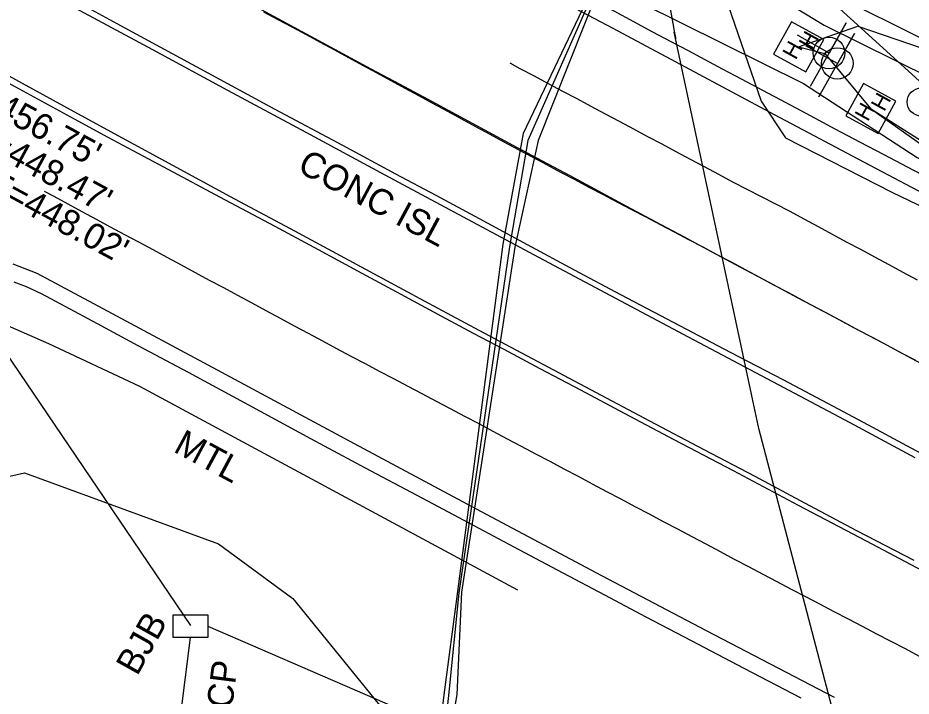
# Model space of a CAD drawing. Extents: x 2074109 to 2077820, y 741079 to 746031.
# Drawn here: x 2075958.1 to 2076097, y 743030.4 to 743136 of the extents above; entities that cross this region are included whole.
import ezdxf

# ---------------------------------------------------------------- set-up
doc = ezdxf.new("R2010")
doc.units = 0
for name, color, linetype in [('Exist Guardrail', 7, 'Continuous'), ('Exist Guardrail Text', 7, 'Continuous'), ('Exist Horizontal Alignment', 7, 'Continuous'), ('Exist Other Culture Anchor (Guy Wire) CELL', 7, 'Continuous'), ('Exist Roads Curbs', 7, 'Continuous'), ('Exist Roads Curbs Text', 7, 'Continuous'), ('Exist Roads EOP', 7, 'Continuous'), ('Exist Roads EOT', 7, 'Continuous'), ('Exist Structure Minor Drop Inlet Top Elevation', 7, 'Continuous'), ('Exist Structure Minor Junction Box', 7, 'Continuous'), ('Exist Structure Minor Junction Box Text', 7, 'Continuous'), ('Exist Structure Minor Pipes RCP 18 Inch Invert', 7, 'Continuous'), ('Exist Structure Minor Pipes RCP 36 Inch', 7, 'Continuous'), ('Exist Structure Minor Pipes RCP 36 Inch Text', 7, 'Continuous'), ('Exist Structure Minor Pipes RCP 42 Inch', 7, 'Continuous'), ('Exist Utilities Gas UG Line SUE LOS B', 7, 'Continuous'), ('Exist Utilities Power Joint Use Telephone CELL', 7, 'Continuous'), ('Exist Utilities Power UG Cable SUE LOS B', 7, 'Continuous'), ('Exist Utilities Telephone UG Conduit SUE LOS B', 7, 'Continuous'), ('Exist Utilities Telephone UG FO SUE LOS B', 7, 'Continuous'), ('Exist Utilities TV Hand Hole CELL', 7, 'Continuous'), ('Exist Utilities TV UG FO Cable SUE LOS B', 7, 'Continuous'), ('Exist Utilities Water UG Line SUE LOS B', 7, 'Continuous'), ('Exist Vegetation Woods Line', 7, 'Continuous')]:
    doc.layers.add(name, color=color, linetype=linetype)

msp = doc.modelspace()

# ---------------------------------------------------------------- linework, layer by layer
at = {"layer": 'Exist Guardrail'}
msp.add_lwpolyline([(2076035.85, 743046.89), (2075977.06, 743078.6), (2075962.92, 743085.25), (2075954.84, 743088.74), (2075948.86, 743090.68), (2075941.12, 743092.48), (2075934.11, 743092.47), (2075927.39, 743091.26), (2075921.51, 743089.22), (2075916.19, 743086.74), (2075911.7, 743083.21), (2075906.18, 743077.24), (2075900.02, 743069.91)], dxfattribs=at)
at = {"layer": 'Exist Horizontal Alignment'}
msp.add_arc((2085431.66, 760592.33), 19842.16, 241.357198, 242.284762, dxfattribs=at)
at = {"layer": 'Exist Other Culture Anchor (Guy Wire) CELL'}
msp.add_circle((2076098.61, 743122.88), 2.18, dxfattribs=at)
at = {"layer": 'Exist Roads Curbs'}
for points in [[(2075956.65, 743143.13), (2075967.73, 743137.15), (2075979.01, 743131.05), (2075990.69, 743124.74), (2076002.87, 743118.19), (2076015.18, 743111.57), (2076027.37, 743105.02), (2076039.05, 743098.75), (2076050.28, 743092.74), (2076062.34, 743086.33), (2076075.49, 743079.38), (2076087.5, 743072.99), (2076097.63, 743067.52)], [(2076041.74, 743142.01), (2076046.99, 743139.13), (2076050.79, 743137.06), (2076053.85, 743135.42), (2076056.83, 743133.83), (2076059.68, 743132.31), (2076062.34, 743130.9), (2076064.95, 743129.51), (2076067.65, 743128.07), (2076070.59, 743126.5), (2076073.92, 743124.72), (2076077.53, 743122.8), (2076081.31, 743120.78), (2076085.18, 743118.73), (2076089.03, 743116.7), (2076092.8, 743114.71), (2076096.45, 743112.79), (2076099.9, 743110.97)], [(2076097.52, 743051.5), (2076088.62, 743056.12), (2076080.48, 743060.44), (2076072.77, 743064.56), (2076064.86, 743068.74), (2076056.4, 743073.2), (2076047.22, 743078.06), (2076038.15, 743082.9), (2076029.87, 743087.32), (2076021.35, 743091.89), (2076011.53, 743097.17), (2076001.15, 743102.76), (2075991.19, 743108.12), (2075982.18, 743112.99), (2075974.38, 743117.24), (2075966.86, 743121.36), (2075958.81, 743125.75), (2075951.51, 743129.74)], [(2076079.91, 743030.08), (2076071.08, 743034.69), (2076062.88, 743038.99), (2076055.83, 743042.7), (2076049.37, 743046.13), (2076042.92, 743049.54), (2076036.05, 743053.19), (2076028.3, 743057.3), (2076020.18, 743061.62), (2076012.17, 743065.89), (2076003.67, 743070.46), (2075994.02, 743075.67), (2075984.61, 743080.75), (2075976.79, 743084.95), (2075970.45, 743088.36), (2075965.44, 743091.07), (2075961.77, 743093.01), (2075959.42, 743094.11), (2075957.49, 743094.84)]]:
    msp.add_lwpolyline(points, dxfattribs=at)
at = {"layer": 'Exist Roads EOP'}
for points in [[(2075942.88, 743151.87), (2075958.64, 743143.23), (2075973.49, 743135.12), (2075986.37, 743128.12), (2075998.08, 743121.79), (2076008.58, 743116.14), (2076016.84, 743111.71), (2076023.1, 743108.36), (2076029.83, 743104.73), (2076037.3, 743100.68), (2076044.63, 743096.74), (2076051.85, 743092.9), (2076060.01, 743088.6), (2076068.99, 743083.89), (2076077.06, 743079.66), (2076084.01, 743076), (2076090.35, 743072.63), (2076096.34, 743069.42), (2076103.09, 743065.8)], [(2076041.9, 743139.05), (2076050.65, 743134.37), (2076062.54, 743128.02), (2076075.76, 743120.96), (2076090.62, 743113.06), (2076107.42, 743104.19)], [(2076098.82, 743049.88), (2076090.09, 743054.5), (2076079.52, 743060.08), (2076069.39, 743065.45), (2076060.2, 743070.31), (2076052.46, 743074.41), (2076045.67, 743078.01), (2076039.35, 743081.37), (2076033.71, 743084.36), (2076028.98, 743086.87), (2076024.02, 743089.51), (2076017.69, 743092.92), (2076010.97, 743096.56), (2076004.85, 743099.86), (2075998.11, 743103.48), (2075989.53, 743108.07), (2075981.59, 743112.32), (2075976.78, 743114.89), (2075972.16, 743117.38), (2075966.88, 743120.23), (2075958.34, 743124.86), (2075950.16, 743129.27)], [(2076085.12, 743030.17), (2076065.2, 743040.55), (2076048.93, 743049.14), (2076030.21, 743059.07), (2076009, 743070.44), (2075989.12, 743081.14), (2075971.37, 743090.69), (2075961.07, 743096.16), (2075957.35, 743097.65)]]:
    msp.add_lwpolyline(points, dxfattribs=at)
at = {"layer": 'Exist Roads EOT'}
for points in [[(2076097.76, 743082.63), (2076095.55, 743083.8), (2076093.34, 743084.98), (2076091.14, 743086.15), (2076088.93, 743087.33), (2076086.72, 743088.5), (2076084.52, 743089.68), (2076082.31, 743090.85), (2076080.1, 743092.03), (2076077.9, 743093.21), (2076075.7, 743094.39), (2076073.5, 743095.58), (2076071.3, 743096.76), (2076069.09, 743097.94), (2076066.88, 743099.11), (2076064.67, 743100.27), (2076062.46, 743101.44), (2076060.24, 743102.6), (2076058.03, 743103.77), (2076055.82, 743104.93), (2076053.61, 743106.1), (2076051.4, 743107.26), (2076049.19, 743108.43), (2076046.97, 743109.6), (2076044.76, 743110.76), (2076042.55, 743111.93), (2076040.35, 743113.1), (2076038.14, 743114.28), (2076035.94, 743115.46), (2076033.73, 743116.64), (2076031.54, 743117.84), (2076029.34, 743119.03), (2076027.14, 743120.22), (2076024.95, 743121.42), (2076022.75, 743122.61), (2076020.55, 743123.8), (2076018.36, 743125), (2076016.16, 743126.19), (2076013.96, 743127.38), (2076011.76, 743128.57), (2076009.57, 743129.77), (2076007.37, 743130.96), (2076005.17, 743132.14), (2076002.97, 743133.33), (2076000.77, 743134.51), (2075998.57, 743135.7), (2075996.37, 743136.89)], [(2076098.01, 743095.14), (2076095.81, 743096.33), (2076093.61, 743097.52), (2076091.41, 743098.71), (2076089.21, 743099.9), (2076087.01, 743101.08), (2076084.81, 743102.27), (2076082.62, 743103.46), (2076080.42, 743104.65), (2076078.22, 743105.84), (2076076, 743106.99), (2076073.77, 743108.13), (2076071.55, 743109.27), (2076069.33, 743110.42), (2076067.12, 743111.6), (2076064.92, 743112.77), (2076062.71, 743113.95), (2076060.51, 743115.13), (2076058.3, 743116.3), (2076056.09, 743117.48), (2076053.89, 743118.66), (2076051.68, 743119.84), (2076049.48, 743121.01), (2076047.27, 743122.19), (2076045.07, 743123.37), (2076042.86, 743124.54), (2076040.65, 743125.72), (2076038.45, 743126.9), (2076036.24, 743128.07), (2076034.68, 743128.91)], [(2076098.36, 743036.58), (2076096.14, 743037.73), (2076093.93, 743038.89), (2076091.71, 743040.05), (2076089.5, 743041.21), (2076087.28, 743042.37), (2076085.07, 743043.53), (2076082.85, 743044.69), (2076080.64, 743045.84), (2076078.42, 743047), (2076076.21, 743048.16), (2076074, 743049.33), (2076071.79, 743050.51), (2076069.58, 743051.68), (2076067.38, 743052.86), (2076065.17, 743054.03), (2076062.96, 743055.2), (2076060.75, 743056.37), (2076058.54, 743057.54), (2076056.33, 743058.71), (2076054.12, 743059.88), (2076051.91, 743061.05), (2076049.7, 743062.22), (2076047.49, 743063.39), (2076045.28, 743064.56), (2076043.08, 743065.73), (2076040.87, 743066.9), (2076038.66, 743068.07), (2076036.45, 743069.24), (2076034.24, 743070.41), (2076032.03, 743071.59), (2076029.83, 743072.76), (2076027.62, 743073.93), (2076025.41, 743075.1), (2076023.2, 743076.27), (2076020.99, 743077.44), (2076018.78, 743078.61), (2076016.57, 743079.78), (2076014.36, 743080.95), (2076012.15, 743082.12), (2076009.94, 743083.29), (2076007.73, 743084.46), (2076005.53, 743085.63), (2076003.32, 743086.82), (2076001.12, 743088), (2075998.92, 743089.19), (2075996.72, 743090.37), (2075994.52, 743091.56), (2075992.32, 743092.74), (2075990.12, 743093.93), (2075987.92, 743095.12), (2075985.72, 743096.3), (2075983.52, 743097.49), (2075981.32, 743098.67), (2075979.11, 743099.86), (2075976.91, 743101.04), (2075974.71, 743102.23), (2075972.51, 743103.42), (2075970.31, 743104.6), (2075968.11, 743105.79), (2075965.91, 743106.98), (2075963.71, 743108.16), (2075962.25, 743108.95)]]:
    msp.add_lwpolyline(points, dxfattribs=at)
at = {"layer": 'Exist Structure Minor Junction Box'}
msp.add_lwpolyline([(2075982.23, 743043.04), (2075987.65, 743043.04), (2075987.65, 743039.52), (2075982.23, 743039.52)], close=True, dxfattribs=at)
at = {"layer": 'Exist Structure Minor Pipes RCP 36 Inch'}
for p, q in [((2075987.65, 743041.28), (2076069.92, 743005.68)), ((2075981.4, 743011.28), (2075984.94, 743039.52))]:
    msp.add_line(p, q, dxfattribs=at)
at = {"layer": 'Exist Structure Minor Pipes RCP 42 Inch'}
msp.add_line((2075912.93, 743147.67), (2075984.95, 743041.39), dxfattribs=at)
at = {"layer": 'Exist Utilities Gas UG Line SUE LOS B'}
msp.add_lwpolyline([(2075996.08, 743328.1), (2076028.05, 743254.56), (2076033.74, 743242.95), (2076036.74, 743229.04), (2076040.38, 743218.46), (2076044.43, 743205.24), (2076049.54, 743192.7), (2076055.99, 743180.15), (2076059.89, 743167.76), (2076068.56, 743138.12), (2076068.53, 743138.04), (2076073.69, 743123.02), (2076077.5, 743117.33), (2076094.04, 743108.87), (2076148.84, 743082.51), (2076220.11, 743045.2), (2076259.6, 743025.74), (2076318.3, 742998.06), (2076360.46, 742978.31), (2076403.47, 742958.09), (2076437.14, 742944.03)], dxfattribs=at)
at = {"layer": 'Exist Utilities Power Joint Use Telephone CELL'}
for p, q in [((2076084.28, 743130.52), (2076084.28, 743130.52)), ((2076085.57, 743128.88), (2076085.57, 743128.88))]:
    msp.add_line(p, q, dxfattribs=at)
for points in [[(2076081.37, 743125.34), (2076086.95, 743135.21), (2076084.29, 743130.51), (2076079.37, 743133.27)], [(2076082.67, 743123.71), (2076088.25, 743133.57), (2076085.59, 743128.87), (2076080.67, 743131.64)]]:
    msp.add_lwpolyline(points, dxfattribs=at)
for centre in [(2076084.27, 743130.52), (2076085.57, 743128.89)]:
    msp.add_circle(centre, 2.45, dxfattribs=at)
at = {"layer": 'Exist Utilities Power UG Cable SUE LOS B'}
msp.add_lwpolyline([(2076006.41, 743187.86), (2076006.4, 743187.87), (2076014.64, 743174.79), (2076032.56, 743157.65), (2076035.3, 743152.7), (2076055.02, 743138.31), (2076080.32, 743125.75), (2076098, 743114.25), (2076150.92, 743086.68), (2076224.69, 743050.77), (2076243.07, 743041.49)], dxfattribs=at)
at = {"layer": 'Exist Utilities Telephone UG Conduit SUE LOS B'}
for points in [[(2075672.89, 743341.39), (2075736.54, 743308.65), (2075796.69, 743278.05), (2075867.04, 743238.5), (2075921.9, 743209.46), (2075960.48, 743187.73), (2076008.51, 743166.58), (2076026.12, 743160.68), (2076048.83, 743145.45), (2076053.46, 743153.14), (2076083.51, 743134.83), (2076100.14, 743126.62), (2076153.6, 743096.75), (2076227.57, 743057.65), (2076265.35, 743038.75), (2076325.02, 743012.99), (2076370.03, 742993.2), (2076407.51, 742976.75), (2076444.05, 742959.06)], [(2076053.46, 743153.14), (2076036.68, 743117.98), (2076033.52, 743100.73), (2076026.46, 743046.66), (2076024.37, 743030.6), (2076022.75, 743016.72), (2076022.37, 743007.18)]]:
    msp.add_lwpolyline(points, dxfattribs=at)
at = {"layer": 'Exist Utilities Telephone UG FO SUE LOS B'}
for points in [[(2075889.86, 743237.93), (2075895.59, 743228.51), (2075924.94, 743209.93), (2075958.41, 743190.94), (2075991.59, 743174.52), (2076008.89, 743165.82), (2076027.41, 743153.76), (2076049.09, 743142.61), (2076053.91, 743141.46), (2076059.01, 743140.99), (2076072.19, 743141.15), (2076089.2, 743137.48), (2076101.24, 743131.5), (2076156.95, 743103.14), (2076158.66, 743102.38), (2076232.03, 743071), (2076268.38, 743053.9), (2076329.12, 743025.97), (2076375.16, 743007.01), (2076410.42, 742991.12), (2076450.75, 742973.66)], [(2076053.46, 743153.14), (2076039.04, 743116.87), (2076035.42, 743100.28), (2076027.12, 743046.58), (2076026.36, 743030.63), (2076024.05, 743016.81), (2076022.37, 743007.18)], [(2076053.46, 743153.14), (2076037.4, 743116.88), (2076034.56, 743100.32), (2076026.69, 743046.45), (2076025.05, 743030.47), (2076023.54, 743016.76), (2076022.37, 743007.18)], [(2076088.16, 743013.29), (2076084.73, 743028.71), (2076073.37, 743072.06), (2076060.17, 743133.75), (2076060.46, 743132.79), (2076059.01, 743140.99)]]:
    msp.add_lwpolyline(points, dxfattribs=at)
at = {"layer": 'Exist Utilities TV Hand Hole CELL'}
for p, q in [((2076079.54, 743131.47), (2076079.54, 743131.47)), ((2076090.77, 743121.87), (2076090.77, 743121.87))]:
    msp.add_line(p, q, dxfattribs=at)
for points in [[(2076080.66, 743127.56), (2076083.44, 743132.59), (2076078.41, 743135.37), (2076075.63, 743130.34), (2076080.66, 743127.56)], [(2076091.89, 743117.96), (2076094.67, 743122.99), (2076089.64, 743125.77), (2076086.86, 743120.74), (2076091.89, 743117.96)]]:
    msp.add_lwpolyline(points, dxfattribs=at)
at = {"layer": 'Exist Utilities TV UG FO Cable SUE LOS B'}
msp.add_line((2076079.54, 743131.47), (2076083.6, 743130.45), dxfattribs=at)
for points in [[(2076079.54, 743131.47), (2076088.75, 743134.71), (2076100.72, 743130.58), (2076230.37, 743064.49), (2076267.06, 743047.02), (2076329.64, 743021), (2076373.86, 743003.6), (2076375.16, 743000.31), (2076408.25, 742984.45), (2076447.17, 742965.86)], [(2076083.6, 743130.45), (2076090.74, 743121.86), (2076099.09, 743116.59), (2076149.07, 743090.83), (2076226.38, 743054.36), (2076264.41, 743037.05), (2076323.79, 743010.38), (2076368.03, 742988.68), (2076370.37, 742987.68), (2076405.31, 742971.65), (2076441.93, 742954.46)], [(2076083.6, 743130.45), (2076090.73, 743121.86), (2076098.84, 743116.1), (2076148.75, 743090.35), (2076226.27, 743053.92), (2076264.15, 743036.52), (2076323.36, 743009.63), (2076368, 742988.68), (2076369.51, 742985.96), (2076404.98, 742971), (2076441.71, 742953.97)]]:
    msp.add_lwpolyline(points, dxfattribs=at)
at = {"layer": 'Exist Utilities Water UG Line SUE LOS B'}
msp.add_lwpolyline([(2075822.78, 743289.56), (2075827.27, 743285.77), (2075840.04, 743277.92), (2075859.15, 743265.03), (2075885.55, 743248.54), (2075912.1, 743233.66), (2075938.18, 743219.55), (2075978.32, 743202.62), (2076004.37, 743190.72), (2076024.72, 743179.9), (2076058.28, 743162.37), (2076071.85, 743150.27), (2076099.45, 743125.15), (2076149.87, 743092.08), (2076225.21, 743053.38), (2076263, 743035.19), (2076322.41, 743007.95), (2076371.93, 742982.13), (2076406.73, 742964.12), (2076444.22, 742949.22), (2076483.69, 742930.03)], dxfattribs=at)
at = {"layer": 'Exist Vegetation Woods Line'}
msp.add_lwpolyline([(2075507.31, 742678.29), (2075568.35, 742703.76), (2075610.97, 742725.09), (2075654.83, 742745.79), (2075688.15, 742767.83), (2075722.03, 742785.8), (2075750.54, 742806.88), (2075781.97, 742834.97), (2075816.18, 742876.22), (2075841.25, 742901.4), (2075859.22, 742923.86), (2075871.34, 742948.51), (2075884.5, 742981.77), (2075900.73, 743026.95), (2075910.16, 743047.34), (2075921.17, 743058.1), (2075942.17, 743061.33), (2075959.14, 743065.18), (2075989.29, 743054.09), (2076000.87, 743045.57), (2076015.5, 743027.61), (2076035.49, 743021.94), (2076059.35, 743010.69)], dxfattribs=at)

# ---------------------------------------------------------------- texts
at = {"layer": 'Exist Guardrail Text'}
msp.add_text('MTL', height=4, rotation=331.6571, dxfattribs=at).set_placement((2075982.12, 743068.53))
at = {"layer": 'Exist Roads Curbs Text'}
msp.add_text('CONC ISL', height=4, rotation=331.757, dxfattribs=at).set_placement((2076001.37, 743112.17))
at = {"layer": 'Exist Structure Minor Drop Inlet Top Elevation'}
msp.add_text("TOP=456.75'", height=4, rotation=331.5083, dxfattribs=at).set_placement((2075941.91, 743127.66))
at = {"layer": 'Exist Structure Minor Junction Box Text'}
msp.add_text('BJB', height=4, rotation=60.742, dxfattribs=at).set_placement((2075976.65, 743033.41))
at = {"layer": 'Exist Structure Minor Pipes RCP 18 Inch Invert'}
for s, p in [("INV IN=448.47'", (2075939.44, 743122.7)), ("INV OUT=448.02'", (2075936.76, 743117.76))]:
    msp.add_text(s, height=4, rotation=331.5083, dxfattribs=at).set_placement(p)
at = {"layer": 'Exist Structure Minor Pipes RCP 36 Inch Text'}
msp.add_text('36" RCP', height=4, rotation=82.8548, dxfattribs=at).set_placement((2075989.76, 743015.23))
at = {"layer": 'Exist Utilities TV Hand Hole CELL'}
for p in [(2076081.62, 743130.87), (2076079.09, 743129.32), (2076092.85, 743121.27), (2076090.32, 743119.72)]:
    msp.add_text('H', height=2.5, rotation=61.1016, dxfattribs=at).set_placement(p)

doc.saveas('drawing.dxf')
